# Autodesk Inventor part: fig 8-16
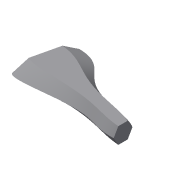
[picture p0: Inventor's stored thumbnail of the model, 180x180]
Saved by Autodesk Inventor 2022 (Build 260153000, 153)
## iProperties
Created: 2004-05
Part Number: fig 8-16
Document SubType Name: Modeling
Designer: CADCIM Technologies
Manufacturer: Standard
Standards Organization: Custom
Density: 1 g/cm^3
Material: Generic
Appearance: Default
Author: CADCIM Technologies
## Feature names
1. Sweep7
## Parameters: d6 = 0, d7 = 0
